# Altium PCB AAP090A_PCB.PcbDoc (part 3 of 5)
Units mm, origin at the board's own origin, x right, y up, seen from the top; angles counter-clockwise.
Board outline 160 x 130 mm, 4 copper layers (Top Layer, Signal Layer 1, Signal Layer 2, Bottom Layer), stack 1.567 mm thick; 507 components, 275 nets, 1462 pads, 1041 vias.
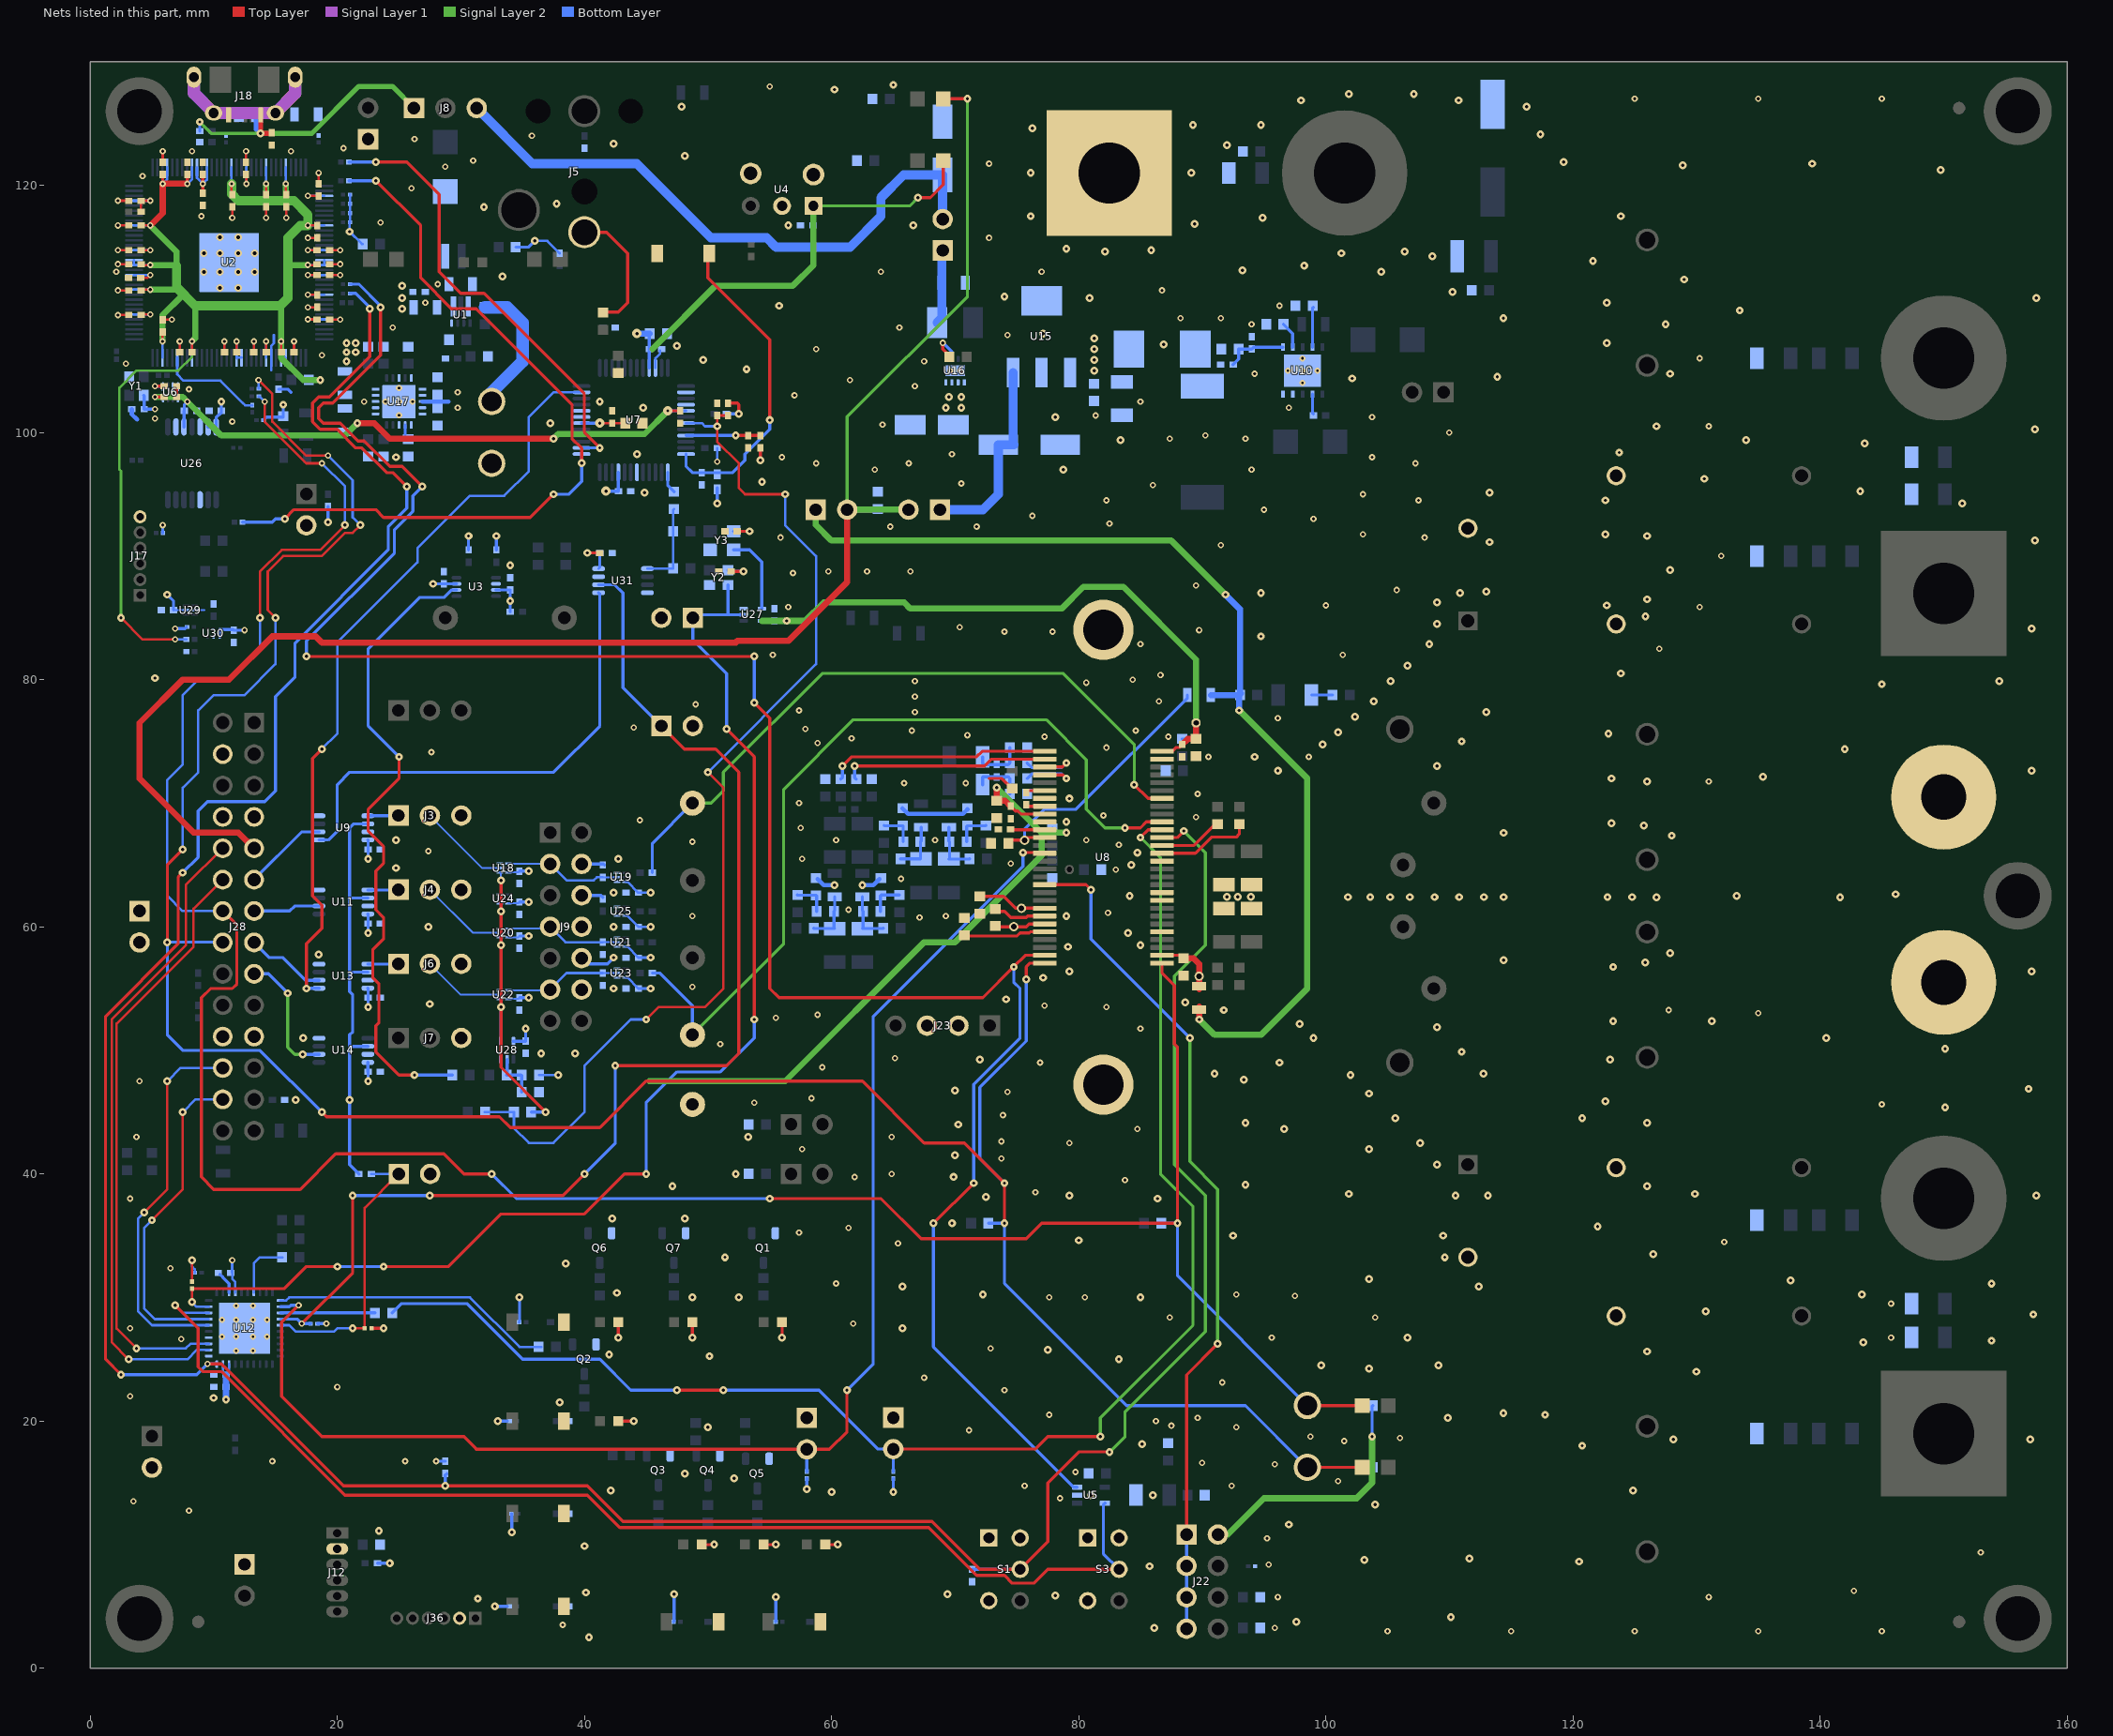
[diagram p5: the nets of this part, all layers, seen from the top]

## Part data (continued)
U27 U28: library part SN74LVC1G14DRLR, "SINGLE SCHMITT-TRIGGER INVERTER, DRL0005A (SOT-5)", Alternate Manufacturer="Texas Instruments"
U29: "DUAL BUFFER/DRIVER WITH OPEN DRAIN OUTPUTS, DSF0006A", Alternate Manufacturer="Texas Instruments"
U30: "Single-Channel, Adjustable Supervisory Circuit in Ultra-Small Package, DRY0006A (USON-6)", Alternate Manufacturer="Texas Instruments", Alternate PartNumber=TPS3897ADRYT
Y1: "OSC, 24 MHz, 2.25 - 3.63 V, SMD", Frequency=24MHz, Frequency Stability=±20ppm, Manufacturer="Abracon Corporation", Supplier Part Number 1=535-13061-1-ND
Y2: "OSC, 24.576 MHz, 2.25 - 3.63 V, SMD", Frequency=24.576MHz, Frequency Stability=±20ppm, Manufacturer="Abracon Corporation", Supplier Part Number 1=535-13231-ND
Y3: "Oscillators, 22.5792MHz, CMOS, 3.3V, SMD", Frequency=22.5792MHz, Frequency Stability=±25ppm, Manufacturer="TXC Corporation", Supplier Part Number 1=887-2303-1-ND
ZZ1 ZZ2 ZZ3: library part AssemblyNote, Alternate Manufacturer=-

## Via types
v1: diameter 0.635, hole 0.254, Top Layer to Bottom Layer, tented both sides, 653 vias
v2: diameter 0.508, hole 0.254, Top Layer to Bottom Layer, tented both sides, 340 vias
v3: diameter 0.5, hole 0.2, Top Layer to Bottom Layer, 24 vias
v4: diameter 0.6, hole 0.3, Top Layer to Bottom Layer, 12 vias
v5: diameter 0.762, hole 0.254, Top Layer to Bottom Layer, tented both sides, 8 vias
v6: diameter 0.457, hole 0.203, Top Layer to Bottom Layer, tented both sides, 4 vias

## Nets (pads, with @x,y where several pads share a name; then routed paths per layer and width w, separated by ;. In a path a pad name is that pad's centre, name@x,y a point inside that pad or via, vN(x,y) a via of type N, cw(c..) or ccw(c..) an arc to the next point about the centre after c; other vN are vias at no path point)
1.0V: C125.1 C126.1 C127.2 C128.2 C129.2 C130.2 C131.2 C132.2 C133.2 C134.2 C135.2 C136.2 C137.2 C138.2 C139.2 C140.2 L1.2 R1.2 R2.2 R140.1 R156.1 U1.4 U2.11 U2.16 U2.17 U2.24 U2.36 U2.41 U2.49 U2.56 U2.60 U2.73 U2.80 U2.81 U2.87 U2.101 U2.102 U2.120 U2.126 | length 126.8
  Top Layer w0.2: v1(2.5,85) 4.25,83.25 v2(6.875,83.25) ; C128.2@4.125,111.5 4.175,111.55 v2(4.875,111.55) ; C129.2@4.125,113.625 4.2,113.55 v2(4.875,113.55) ; C130.2@4.125,116.75 v2(4.875,116.75) ; v2@5.875,107.35 v2(5.85,107.375) 5.85,108.1 C140.2@5.875,108.125 ; v2(5.875,120.125) C135.2@5.875,120.875 ; C139.2@8.25,106.5 v2(8.25,107.375) ; v2(11.45,120.125) 11.45,119.3 C133.2@11.5,119.25 ; C131.2@14.25,119.25 v2(14.25,120.125) ; v2(15.45,107.375) 15.45,106.55 C138.2@15.5,106.5 ; v2(15.85,120.125) 15.85,119.275 C132.2@15.875,119.25 ; v2(17.625,111.15) 18.35,111.15 C137.2@18.375,111.125 ; v2(17.625,113.55) 18.3,113.55 C136.2@18.375,113.625 ; v2(17.625,116.75) C127.2@18.375,116.75
  Top Layer w0.25: v2(7.875,120.125) C134.2@7.875,120.875
  Top Layer w0.5: v2(4.875,116.75) 5.875,117.75 v2(5.875,120.125) v2(7.875,120.125)
  Signal Layer 2 w0.2: v1(2.5,85) 2.5,96.875 2.375,97 2.375,103.625 3.75,105 7.125,105 8.25,106.125 v2(8.25,107.375)
  Signal Layer 2 w0.5: v2(4.875,111.55) 6.8,111.55 7,111.75 ; v2(4.875,113.55) 6.95,113.55 7,113.5 7,114.625 v2(4.875,116.75) ; v2(5.85,107.375) 5.85,109.475 7.5,111.125 ; v2(8.25,107.375) 8.5,107.625 8.5,110.25 ; 14.25,118.75 v2(14.25,120.125) ; 15.375,110.375 15.438,110.312 15.45,110.3 v2(15.45,107.375) 15.45,106.05 17.25,104.25 v1(18.625,104.25) ; v2(15.85,120.125) 15.85,118.9 16,118.75 ; 16,113.5 16.05,113.55 v2(17.625,113.55)
  Signal Layer 2 w0.75: 7,113.5 7,111.75 8.5,110.25 15.375,110.25 15.438,110.312 16,110.875 16,113.5 16,115.75 17,116.75 v2(17.625,116.75) 17.625,117.625 16.5,118.75 16,118.75 14.25,118.75 12,118.75 11.45,119.3 v2(11.45,120.125)
  Bottom Layer w0.2: U2.11@3.55,111.55 v2(4.875,111.55) ; U2.16@3.55,113.55 U2.17@3.55,113.95 ; U2.24@3.55,116.75 v2(4.875,116.75) ; U2.16@3.625,113.55 v2(4.875,113.55) ; U2.126@5.85,106.05 v2(5.85,107.375) ; v2(5.875,120.125) 6.25,120.5 U2.36@6.25,121.45 ; v2(6.875,83.25) R156.1@7.795,83.25 ; v2(7.875,120.125) 8.25,120.5 U2.41@8.25,121.45 ; U2.120@8.25,106.05 v2(8.25,107.375) ; v2(11.45,120.125) U2.49@11.45,121.45 ; v2(14.25,120.125) U2.56@14.25,121.45 ; U2.102@15.45,106.05 15.8,106.05 U2.101@15.85,106 ; U2.102@15.45,106.125 v2(15.45,107.375) ; v2(15.85,120.125) U2.60@15.85,121.45 ; R140.1@17.5,104.05 R140.1@17.7,104.25 v1(18.625,104.25) ; v2(17.625,111.15) U2.87@18.95,111.15 ; v2(17.625,113.55) U2.81@18.95,113.55 U2.80@18.95,113.95 ; v2(17.625,116.75) U2.73@18.95,116.75
  other v1: 25.25,110 25.25,110.875 25.25,111.875
1.8V: C3.1 C89.2 C146.2 C147.2 R8.1 U6.8 U7.17 U17.11 U17.12 U26.3 | length 50.5
  Top Layer w0.25: v2(5.25,102.875) 5.875,102.875 C146.2@6,102.75 ; v5(46.75,101.75) C89.2@47.5,101.75
  Top Layer w0.5: v1(21.625,100.75) 23,100.75 24.25,99.5 v1(37.5,99.5)
  Signal Layer 2 w0.5: v2(5.25,102.875) 7.5,102.875 v2(7.875,102.5) 10.625,99.75 20.625,99.75 v1(21.625,100.75) ; v1(37.5,99.5) 37.875,99.875 44.875,99.875 v5(46.75,101.75)
  Bottom Layer w0.25: v2(5.25,102.875) U6.8@5.875,102.875 ; U26.3@7.6,100.45 7.6,101.75 C147.2@7.625,101.75 7.625,102.25 v2(7.875,102.5) ; v5(46.75,101.75) U7.17@48.225,101.75
3.3V: C17.2 C18.1 C27.2 C37.2 C40.2 C45.2 C54.2 C55.2 C56.2 C58.2 C59.2 C60.1 C61.1 C69.2 C70.2 C71.1 C72.1 C74.2 C80.2 C87.1 C88.2 C90.2 C92.1 C93.1 C94.2 C99.2 C100.2 C101.2 C102.2 C108.2 C109.2 C110.2 C111.2 C112.2 C113.2 C114.2 C115.2 C116.2 C117.2 C118.2 C119.2 C120.2 C121.2 C122.2 C123.2 C143.2 C144.2 C145.2 C148.2 C149.2 C156.2 D4.1 D5.1 D6.1 D7.1 D8.1 D14.1 D15.1 D16.1 J11.1 J16.1 J22.2 J28.7 J28.8 R5.2 R6.1 R11.2 R19.1 R20.1 R22.1 R23.2 R25.1 R38.1 R39.1 R40.1 R41.2 R42.1 R44.1 R45.1 R66.2 R78.2 R79.2 R80.1 R81.2 R82.2 R90.1 R91.1 R92.1 R101.1 R110.1 R114.2 R119.2 R120.2 R124.2 R129.2 R133.2 R136.2 R137.2 R138.2 R139.2 R141.1 R149.1 R150.1 R155.1 R165.2 R167.1 TP12.1 U2.6 U2.14 U2.19 U2.29 U2.42 U2.44 U2.52 U2.67 U2.78 U2.83 U2.92 U2.105 U2.110 U2.111 U3.3 U3.7 U4.1 U6.1 U7.9 U7.33 U7.42 U8.9 U8.56 U9.8 U11.8 U12.14 U12.38 U12.39 U13.8 U14.8 U17.14 U17.15 U18.6 U19.6 U20.6 U21.6 U22.6 U23.6 U24.6 U25.6 U26.6 U26.7 U27.5 U28.5 U29.5 U30.1 U30.6 U31.8 Y1.4 Y2.4 Y3.4 | length 309.9
  Top Layer w0.2: C100.2@4.1,112.5 4.625,112.5 v2(4.875,112.75) ; C80.2@4.125,109.5 4.175,109.55 v2(4.875,109.55) ; C99.2@4.125,114.75 v2(4.875,114.75) ; R110.1@4.125,117.875 C102.2@4.125,118.75 v2(4.875,118.75) ; 8.25,31.5 v1(8.25,33) ; v2(11.85,107.375) 11.85,106.525 C54.2@11.875,106.5 ; C27.2@12.625,120.875 12.65,120.85 v2(12.65,120.125) ; C74.2@14.25,106.5 v2(14.25,107.375) ; v2(17.625,109.15) 18.35,109.15 C58.2@18.375,109.125 ; v2(17.625,112.75) C101.2@18.375,112.75 ; v2(17.625,114.75) C40.2@18.375,114.75 ; v2(17.625,119.15) 18.475,119.15 C45.2@18.5,119.125 ; v1(40.25,90.25) R82.2@41.25,90.25 ; v5(41.25,100.75) C88.2@42.25,100.75 C87.1@43.3,100.75
  Top Layer w0.25: v2(5.25,103.75) C144.2@5.875,103.75 ; C17.2@9.125,119.375 v2(9.125,120.125) C37.2@9.125,120.875 ; R5.2@22.78,27.5 v1(23.75,27.5) ; D4.1@42.75,20 v1(44,20) ; v1(42.75,26.75) D8.1@42.75,28 ; v1(48.75,26.75) D15.1@48.75,28 ; D5.1@49.5,10 v1(50.5,10) ; R120.2@51.625,102.375 52.375,102.375 52.5,102.25 v1(52.5,101.5) ; C118.2@51.875,88.75 v1(52.875,88.75) ; C119.2@52.375,92 v1(53.375,92) ; v1(54.25,97.75) R119.2@54.25,98.75 ; D6.1@54.5,10 v1(55.5,10) ; v1(56,26.75) D16.1@56,28 ; D7.1@59.5,10 v1(60.5,10) ; v1(67,119) 68,119 69.05,120.05 D14.1@69.05,122 ; C72.1@74.5,69.75 74.875,69.375 75.075,69.375 75.333,69.117 U8.9@77.25,69.117 ; U8.56@86.75,74.197 87.572,74.197 87.875,74.5 88.125,74.5 C61.1@88.375,74.75
  Top Layer w0.5: C71.1@73.325,70.25 C71.1@73.375,70.2 74.05,70.2 C72.1@74.5,69.75 ; C71.1@73.375,70.25 v1(73.375,71.25) ; C61.1@88.375,74.75 88.825,75.2 C60.1@89.5,75.2 TP12.1@89.5,76.5
  Signal Layer 2 w0.25: U4.1@58.54,118.33 66.33,118.33 v1(67,119)
  Signal Layer 2 w0.5: 45.25,47.5 56.25,47.5 67.5,58.75 70,58.75 77,65.75 77,67.625 ; 45.5,106.75 50.625,111.875 56.875,111.875 58.54,113.54 U4.1@58.54,118.33 ; 54.375,84.75 v1(56.375,84.75) 57.875,84.75 59.375,86.25 65.875,86.25 66.375,85.75 78.625,85.75 80.375,87.5 83.625,87.5 89.5,81.625 TP12.1@89.5,76.5 ; v1(73.375,71.25) 77,67.625 ; v1(79,67.625) 77,67.625 ; J22.2@91.27,10.81 92.06,10.81 95,13.75 102.5,13.75 103.75,15 v1(103.75,18.75)
  Bottom Layer w0.15: C149.2@6.75,85.625 U29.5@7.785,85.625 ; U22.6@33.84,54.15 34.65,54.15 C110.2@34.75,54.25 ; U20.6@33.84,59.15 34.65,59.15 C111.2@34.75,59.25 ; U24.6@33.84,61.9 34.65,61.9 C112.2@34.75,62 ; U18.6@33.84,64.4 34.65,64.4 C113.2@34.75,64.5
  Bottom Layer w0.2: U2.6@3.55,109.55 v2(4.875,109.55) ; U2.14@3.55,112.75 v2(4.875,112.75) ; U2.19@3.55,114.75 v2(4.875,114.75) ; U2.29@3.55,118.75 v2(4.875,118.75) ; v1(8.25,33) 8.25,32.5 8.47,32.28 R114.2@8.47,32 ; U2.42@8.65,121.45 8.65,120.6 v2(9.125,120.125) 9.45,120.45 U2.44@9.45,121.45 ; U12.39@10.75,24.6 10.75,24 C56.2@11,23.75 11.25,24 U12.38@11.25,24.6 ; C120.2@11.5,32 11.5,31.5 11.75,31.25 U12.14@11.75,30.4 ; U2.111@11.85,106.05 v2(11.85,107.375) ; U2.111@11.875,106 11.925,106.05 U2.110@12.25,106.05 ; v2(12.65,120.125) U2.52@12.65,121.45 ; U2.105@14.25,106.05 v2(14.25,107.375) ; v2(17.625,109.15) U2.92@18.95,109.15 ; v2(17.625,112.75) U2.83@18.95,112.75 ; v2(17.625,114.75) U2.78@18.95,114.75 ; v2(17.625,119.15) U2.67@18.95,119.15 ; R139.2@21,117 21.03,117.03 R138.2@21.03,117.75 ; R138.2@21,117.75 21.03,117.78 R137.2@21.03,118.5 ; R137.2@21,118.5 21.03,118.53 R136.2@21.03,119.25 ; R139.2@21.03,117 21,116.97 v1(21,116.25) 22,115.25 R141.1@22.05,115.25 ; v1(36,115.5) 37,115.5 R23.2@38,114.5 ; R11.2@36.325,48 v1(37.875,48) ; v1(40.25,90.25) C156.2@41.25,90.25 41.25,89.075 U31.8@41.15,88.975 ; U23.6@43.34,55.9 43.475,55.9 C117.2@44.375,55 v1(45.375,55) ; U21.6@43.34,58.4 43.475,58.4 C116.2@44.375,57.5 v1(45.375,57.5) ; U25.6@43.34,60.9 43.475,60.9 C114.2@44.375,60 v1(45.375,60) ; U19.6@43.34,63.65 43.475,63.65 C115.2@44.375,62.75 v1(45.375,62.75) ; v2(50.75,97.625) R22.1@50.75,98.75 ; C18.1@58.5,116.75 58.5,118.25 U4.1@58.625,118.375 ; R165.2@88.375,75.2 89.2,75.2 89.5,75.5 TP12.1@89.5,76.5
  Bottom Layer w0.25: Y1.4@4.35,103 4.375,102.975 C143.2@4.375,101.875 v2(5.25,101.875) ; v2(5.25,103.75) U6.1@5.875,103.75 ; R149.1@5.875,91.875 v2(5.875,92.5) ; v1(6.25,86.875) 6.75,86.375 C149.2@6.75,85.625 ; v2(6.875,84.125) 7.67,84.125 R155.1@7.795,84.25 ; U26.6@9.55,100.45 U26.7@10.2,100.45 10.2,101.2 10.625,101.625 C145.2@10.625,101.75 v1(10.625,102.5) ; U30.1@10.5,83.475 U30.6@10.5,84.05 11.575,84.05 C148.2@11.625,84 v2(12.5,84) ; C120.2@11.5,32 v2(11.5,33) ; R150.1@14.03,101 14.28,101.25 R167.1@15.625,101.25 ; R167.1@15.625,101.325 v1(15.625,102.25) ; R66.2@18.405,27.875 v2(19.125,27.875) ; v1(19.25,92.75) R80.1@19.25,94 ; U14.8@22.475,49.025 22.475,48.275 C108.2@22.5,48.25 v1(22.5,47.5) ; U13.8@22.475,55.025 22.5,55 C70.2@22.5,54.25 v1(22.5,53.5) ; U11.8@22.475,61.025 22.5,61 C69.2@22.5,60.25 v1(22.5,59.5) ; U9.8@22.475,67.025 22.5,67 C59.2@22.5,66.25 v1(22.5,65.5) ; R41.2@23.25,8.5 v1(24.25,8.5) ; v1(27.75,87.75) C121.2@28.625,87.75 U3.7@29.65,87.75 ; v2(28,16.75) R92.1@28.75,16.75 ; R124.2@30.625,90.5 v1(30.625,91.625) ; v1(32.75,5) 33.75,5 ; U3.3@32.85,87.25 C123.2@34,87.25 v1(34,86.375) R81.2@34,85.5 ; R133.2@32.875,90.5 v1(32.875,91.625) ; v1(33,20) 33.75,20 ; R40.1@34.095,12.5 34.125,12.47 v1(34.125,11) ; U28.5@34.25,50.74 35.24,50.74 C109.2@35.25,50.75 v1(35.25,51.75) ; R19.1@34.45,115 35.5,115 v1(36,115.5) ; R38.1@34.72,28 34.75,28.03 v1(34.75,30) ; C110.2@34.75,54.25 v1(35.5,54.25) ; C111.2@34.75,59.25 v1(35.5,59.25) ; C112.2@34.75,62 v1(35.5,62) ; C113.2@34.75,64.5 v1(35.5,64.5) ; U7.42@39.775,100.75 v5(41.25,100.75) ; v5(41.75,95.25) C90.2@42.75,95.25 U7.33@42.75,96.775 ; U7.9@45.25,105.225 45.25,107.95 C93.1@45.3,108 ; R45.1@47.22,3.75 47.25,3.78 v1(47.25,6) ; v1(50.75,94.25) R25.1@50.75,95.5 ; R20.1@51.5,101.5 v1(52.5,101.5) ; Y2.4@51.625,88.85 51.725,88.75 v1(52.875,88.75) ; Y3.4@52.075,92 v1(53.375,92) ; U27.5@54.365,84.75 C122.2@55.375,84.75 v1(56.375,84.75) ; R44.1@55.47,3.75 55.5,3.78 v1(55.5,5.75) ; v1(58,14.5) R90.1@58,15.345 R90.1@58,15.375 ; v1@65,14.5 R91.1@65,15.345 R91.1@65,15.375 ; R101.1@77.875,67.95 78.2,67.625 v1(79,67.625) ; R79.2@103.8,16.25 103.75,16.3 v1(103.75,18.75) 103.75,21.2 R78.2@103.8,21.25
  Bottom Layer w0.5: v1(11,21.75) C55.2@11,22.75 C56.2@11,23.75 ; v5(44.25,108) C93.1@45.3,108
  other v1: 65,14.25 20.75,105.75 20.75,106.5 21.5,106.5 20.75,107.25 21.5,107.25
5V: C2.1 C91.1 C124.1 D17.1 R63.1 TP5.1 U1.7 U17.1 U17.2 U17.4 U17.5 U17.6 U17.20 | length 11
  Bottom Layer w1: R63.1@31.95,110.15 31.975,110.125 33.75,110.125 35,108.875 35,105.75 32.5,103.25 TP5.1@32.5,102.5
5V-USB: C142.2 J8.1 J18.1 R145.2 R157.2 | length 24.7
  Top Layer w0.4: J18.1@13.8,125.7 v1(13.8,124.2) R157.2@14.7,124.2
  Signal Layer 2 w0.25: v1(8.875,125.125) 9.375,124.625 9.8,124.2 v1(13.8,124.2)
  Signal Layer 2 w0.4: v1(13.8,124.2) 17.95,124.2 21.75,128 24.46,128 J8.1@26.21,126.25
  Bottom Layer w0.25: R145.2@8.875,124.375 v1(8.875,125.125)
  Bottom Layer w0.4: C142.2@13.45,125.55 13.45,124.55 v1(13.8,124.2)
5V-VR: C86.1 J8.3 J29.2 | length 49.3
  Bottom Layer w0.75: J8.3@31.29,126.25 35.79,121.75 44.25,121.75 50.25,115.75 54.75,115.75 55.5,115 61.5,115 64,117.5 64,119 65.85,120.85 C86.1@69,120.85 J29.2@69,117.27
12V: C84.2 D13.1 J20.2 J27.2 J28.9 | length 130.8
  Top Layer w0.25: D13.1@69.05,127 v1(71,127)
  Top Layer w0.5: J28.9@13.27,66.35 11.995,67.625 8.375,67.625 4,72 4,76.5 7.5,80 11.25,80 14.75,83.5 18.25,83.5 18.75,83 52.25,83 52.375,83.125 56.5,83.125 61.25,87.875 J20.2@61.25,93.5
  Signal Layer 2 w0.25: J20.2@61.27,93.75 61.27,101.27 71,111 v1(71,127)
  Signal Layer 2 w0.5: J20.2@61.27,93.75 J27.2@66.23,93.75
  Bottom Layer w0.5: J20.2@61.27,93.75 C84.2@63.75,93.75
15V: C38.1 C83.1 C85.1 J25.2 U15.1 U16.2 U16.3
  other v1: 69.25,102 70.5,102 69.5,102.875 70.5,102.875 81.25,105 81.25,105.875 81.25,106.75 81.25,107.625
15V-VR: C34.1 J25.1 L9.2 R58.2
\CLIP_OTW: D9.2 J28.14 R104.2 R163.1 TP15.1 U8.29 | length 212.9
  Top Layer w0.2: v1(13.75,85) 13.75,88.75 15.5,90.5 18.625,90.5 v1(20.625,92.5) ; v2(14.125,102.5) 14.125,100.875 17.5,97.5 v2(18.75,97.5)
  Top Layer w0.25: J28.14@10.73,61.27 11.875,60.125 11.875,55.375 11.5,55 9.75,55 9,54.25 9,39.75 10,38.75 17,38.75 19.875,41.625 28.625,41.625 30.25,40 v1(32.5,40) ; v1(55,38) 64,38 67.25,34.75 75.75,34.75 77,36 v1(88,36) 88,50.25 87.75,50.5 87.75,55.25 86.75,56.25 U8.29@86.75,57.052 ; TP15.1@98.5,21.25 D9.2@102.95,21.25
  Bottom Layer w0.2: J28.14@10.73,61.27 7.48,61.27 6.25,62.5 6.25,71.875 7.5,73.125 7.5,78.75 8.75,80 11.25,80 11.375,80.125 13.75,82.5 v1(13.75,85) ; R163.1@13.655,102.92 13.705,102.92 v2(14.125,102.5) ; v2(18.75,97.5) 20.625,95.625 v1(20.625,92.5)
  Bottom Layer w0.25: v1(32.5,40) 34.5,38 v1(55,38) ; R104.2@86.7,36 v1(88,36) 88,31.75 TP15.1@98.5,21.25
\DAC_MUTE: C151.2 R92.2 R161.1 S1.5 U8.45 U12.40 | length 266.7
  Top Layer w0.25: v1(2.5,23.75) 1.25,25 1.25,52.75 7.125,58.625 7.125,64 v1(7.5,64.375) ; v2(9.5,24.625) 10.625,24.625 10.8,24.45 10.811,24.45 20.511,14.75 v1(28.75,14.75) 40.25,14.75 43.125,11.875 68.125,11.875 72,8 S1.5@75.27,8 77.5,10.23 77.5,15 80,17.5 v1(82.5,17.5) ; v1(22.625,110) 22.625,106.125 19.375,102.875 18.5,102.875 18,102.375 18,100.875 18.625,100.25 20,100.25 21.5,98.75 22,98.75 24,96.75 24.5,96.75 v1(25.625,95.625) ; U8.45@86.75,67.212 87.963,67.212 v1(88.5,67.75)
  Signal Layer 2 w0.25: v1(82.5,17.5) 83.75,18.75 83.75,20.75 90.25,27.25 90.25,38.25 87.75,40.75 87.75,56 90.25,58.5 90.25,66 v1(88.5,67.75)
  Bottom Layer w0.25: v1(2.5,23.75) 8.625,23.75 v2(9.5,24.625) 10.225,24.625 U12.40@10.25,24.6 ; v1(7.5,64.375) 8.75,65.625 8.75,69.375 9.5,70.125 14.125,70.125 15,71 15,78.625 16.581,80.206 16.581,82.956 24.125,90.5 24.125,92.375 25.625,93.875 v1(25.625,95.625) ; R161.1@21.03,111.25 21.5,111.25 22.625,110.125 v1(22.625,110) ; v1(28.75,14.75) 28.75,15.625 R92.2@28.875,15.75 ; C151.2@71.375,8 S1.5@75.27,8
\FAULT: D10.2 J28.16 R103.2 R162.1 TP16.1 U8.28 | length 215.1
  Top Layer w0.2: v2(13.625,104.25) 14.75,103.125 14.75,100.875 17.499,98.126 v2(19.25,98.126) ; v1(15,85) 14.375,85.625 14.375,88.75 15.625,90 18.75,90 20.625,91.875 21.25,91.875 v1(21.875,92.5)
  Top Layer w0.25: v1(6.25,58.75) 6.25,65 v1(7.5,66.25) ; v1(18.75,45) 19.125,44.625 33.125,44.625 34,43.75 41.25,43.75 45,47.5 62.5,47.5 67.5,42.5 70.75,42.5 v1(74,39.25) v1(74,36) ; v1(75.75,55.75) 75.75,56.75 76.052,57.052 U8.28@77.25,57.052 ; TP16.1@98.5,16.25 D10.2@102.95,16.25
  Bottom Layer w0.2: v1@7.5,66.375 7.5,71.25 8.75,72.5 8.75,77.5 10,78.75 12.5,78.75 15,81.25 v1(15,85) ; v2(13.625,104.25) 13.625,103.575 R162.1@13.655,103.545 ; v2(19.25,98.126) v2@19.374,98.126 ; v2@19.375,98.125 19.375,98 21.25,96.125 21.25,93.125 v1(21.875,92.5)
  Bottom Layer w0.25: J28.16@10.73,58.73 10.71,58.75 v1(6.25,58.75) 6.25,51.25 7.515,49.985 13.765,49.985 v1(18.75,45) ; R103.2@72.7,36 v1(74,36) 74,31.125 83.875,21.25 93.5,21.25 TP16.1@98.5,16.25 ; v1(74,39.25) 72,41.25 72,47 75.75,50.75 v1(75.75,55.75)
\FREQ-SEL: U27.4 Y3.1 | length 6.5
  Bottom Layer w0.25: Y3.1@52.075,90.5 53.375,90.5 54.365,89.51 U27.4@54.365,85.75
\I2S-BUF-EN: R168.2 U18.1 U20.1 U22.1 U24.1 U28.4 | length 26.9
  Top Layer w0.25: v1(33.25,63.75) v1(33.25,61.25) v1(33.25,58.5) v1(33.25,53.5) 33.25,48.625 v1(36.875,45)
  Bottom Layer w0.15: U22.1@33.16,54.15 33.25,54.06 v1(33.25,53.5) ; U20.1@33.16,59.15 33.25,59.06 v1(33.25,58.5) ; U24.1@33.16,61.9 33.25,61.81 v1(33.25,61.25) ; U18.1@33.16,64.4 33.25,64.31 v1(33.25,63.75)
  Bottom Layer w0.25: U28.4@33.25,50.74 v1(33.25,53.5) ; R168.2@35.7,45 v1(36.875,45)
\MUTE-AIB: J28.12 U12.3 | length 48.2
  Top Layer w0.2: v1(3.75,25.875) 2.15,27.475 2.15,52.15 8.375,58.375 8.375,61.455 J28.12@10.73,63.81
  Bottom Layer w0.2: v1(3.75,25.875) 7.75,25.875 8.125,26.25 U12.3@9.6,26.25
\RESET-AMP: R160.1 U5.3 U8.27 | length 180.9
  Top Layer w0.25: v1(17.5,81.875) v1(53.75,81.875) ; v1(23.5,110.125) 23.5,106.25 19.625,102.375 18.875,102.375 18.5,102 18.5,101.125 18.875,100.75 20.25,100.75 21.688,99.312 22.188,99.312 24.25,97.25 25.25,97.25 v1(26.875,95.625) ; v1(53.75,78.125) 55,76.875 55,55 55.75,54.25 72.25,54.25 v1(74.75,56.75) 75.687,57.687 U8.27@77.25,57.687 ; v1(68.25,36) v1(71.5,39.25)
  Bottom Layer w0.25: v1(17.5,81.875) 17.5,83.125 24.625,90.25 24.625,92.125 26.125,93.625 26.125,94.875 v1(26.875,95.625) ; R160.1@21.03,112 21.75,112 23.5,110.25 v1(23.5,110.125) ; v1(53.75,78.125) v1(53.75,81.875) ; v1(68.25,36) 68.25,26 79.6,14.65 U5.3@79.875,14.65 ; v1(71.5,39.25) 71.5,47.25 75.25,51 75.25,55 74.75,55.5 v1(74.75,56.75)
\RST-AIB: J28.10 U12.2 | length 52.4
  Top Layer w0.2: v1(3.125,25) 1.75,26.375 1.75,52.5 7.75,58.5 7.75,63.37 J28.10@10.73,66.35
  Bottom Layer w0.2: v1(3.125,25) 7.875,25 8.625,25.75 U12.2@9.6,25.75
\RST-AMP: S3.5 U5.5 U12.8 | length 96.9
  Top Layer w0.25: v1(6.875,29.375) 8.75,27.5 8.75,24.375 9.125,24 10.625,24 20.625,14 40.25,14 42.875,11.375 67.875,11.375 71.75,7.5 74,7.5 74.625,6.875 76.375,6.875 77.5,8 S3.5@83.27,8
  Bottom Layer w0.2: v1(6.875,29.375) 7.5,28.75 U12.8@9.6,28.75
  Bottom Layer w0.25: U5.5@82.125,13.35 82,13.225 82,9.27 S3.5@83.27,8
\SPDIF-RESET: C24.2 R25.2 S2.2 U7.24 | length 26.1
  Top Layer w0.25: S2.2@50.1,114.5 50,114.4 50,112.5 55,107.5 v1(55,101)
  Bottom Layer w0.25: U7.24@48.225,98.25 48.225,97.275 48.75,96.75 C24.2@49.5,96.75 52,96.75 53,97.75 53,98.25 55,100.25 v1(55,101)
\TRST: R147.1 U2.123 | length 8.5
  Bottom Layer w0.2: U2.123@7.05,106.05 7.05,104.7 7.55,104.2 10.55,104.2 12.375,102.375 12.55,102.2 R147.1@13.125,102.2
A0-SRC: R10.1 R120.1 R122.1 R168.1 U7.19 | length 87.7
  Top Layer w0.2: v1(45,52.5) 46,53.5 49.75,53.5 51.25,55 51.25,71.25 v1(50,72.5) ; R120.1@51.625,101.375 R122.1@50.75,101.375 v1(50.75,100.5) 50.75,99.25 52.5,97.5 52.5,95.5 53,95 v1(56.25,95)
  Bottom Layer w0.2: R10.1@31.95,45 R168.1@34.3,45 34.3,43.7 35.5,42.5 37.5,42.5 40,45 40,48.75 43.75,52.5 v1(45,52.5) ; U7.19@48.225,100.75 49.5,100.75 49.75,100.5 v1(50.75,100.5) ; v1(50,72.5) 58.75,81.25 58.75,90 56.25,92.5 v1(56.25,95)
A1-SRC: R119.1 R121.1 U7.21 | length 6
  Top Layer w0.25: v1(52.25,99.75) R121.1@53.25,99.75 R119.1@54.25,99.75
  Bottom Layer w0.25: U7.21@48.225,99.75 v1(52.25,99.75)
ADR: J19.2 R62.1 R91.2 U8.46 | length 120.1
  Top Layer w0.25: v1(47.5,22.5) v1(51.25,22.5) ; J19.2@65,17.73 76.48,17.73 77.5,18.75 v1(81.75,18.75) ; v1(85,67.222) 85.625,67.847 U8.46@86.75,67.847
  Signal Layer 2 w0.25: v1(81.75,18.75) 81.75,20.25 89.25,27.75 89.25,37.375 86.625,40 86.625,65.597 v1(85,67.222)
  Bottom Layer w0.25: R62.1@24.45,28.75 25.2,29.5 30.5,29.5 35,25 41.25,25 43.75,22.5 v1(47.5,22.5) ; v1(51.25,22.5) 59,22.5 63.77,17.73 J19.2@65,17.73 R91.2@65,15.905
ADR-MCU: R62.2 U12.23 | length 7.7
  Bottom Layer w0.25: U12.23@15.4,28.75 R62.2@23.05,28.75
AVDD: C63.2 TP11.1 U8.23 | length 4.1
  Top Layer w0.25: C63.2@73.25,60.05 73.3,60 TP11.1@74.75,60 75.75,60 75.978,60.227 U8.23@77.25,60.227
BCLK-EXT: J28.13 U11.2 | length 5.4
  Bottom Layer w0.25: J28.13@13.27,61.27 16.145,61.27 16.55,61.675 U11.2@18.525,61.675
BCLK-IBC: J9.7 R116.2 U20.4 U21.2 | length 9.4
  Bottom Layer w0.15: U20.4@33.84,59.85 37.08,59.85 J9.7@37.23,60 ; R116.2@41.5,58.75 U21.2@42.66,58.75
  Bottom Layer w0.2: J9.7@37.23,60 38.48,58.75 R116.2@41.5,58.75
BCLK-MUX: J4.1 U11.5 | length 2.5
  Bottom Layer w0.25: U11.5@22.475,62.975 24.935,62.975 J4.1@24.96,63
BCLK-PSIA: J4.2 U20.2 | length 7.1
  Bottom Layer w0.15: J4.2@27.5,63 31,59.5 U20.2@33.16,59.5
BCLK-USB: R143.1 R151.1 U7.37 | length 64.6
  Top Layer w0.25: v1(15.75,93) 16.5,93.75 23.125,93.75 23.75,93.125 35.625,93.125 v1(37.5,95) ; v1(23.125,120.375) 26.75,116.75 26.75,112.5 29.25,110 31.25,110 39,102.25 39,99.5 39.775,98.725 v1(39.775,97.525)
  Bottom Layer w0.25: R151.1@12.33,92.75 14.75,92.75 15,93 v1(15.75,93) ; R143.1@20.955,120.375 v1(23.125,120.375) ; v1(37.5,95) 38.75,95 39.775,96.025 v1(39.775,97.525) U7.37@39.775,98.25
C_START: C78.1 U8.24 | length 6.7
  Top Layer w0.25: C78.1@70.75,59.3 70.8,59.25 75,59.25 75.25,59.5 76,59.5 76.092,59.592 U8.24@77.25,59.592 U8.24@77.282,59.625
COAX-LED: R109.2 U12.17 | length 4.9
  Bottom Layer w0.2: U12.17@13.25,30.4 13.25,32.75 13.75,33.25 R109.2@15.55,33.25
DAC_OUTA+: R95.1 U8.3 | length 5.4
  Top Layer w0.25: U8.3@77.25,72.927 78.677,72.927 v1(79,73.25)
  Bottom Layer w0.25: R95.1@75.825,73.25 76.2,72.875 78.625,72.875 v1(79,73.25)
DAC_OUTA-: R98.1 U8.4 | length 5.4
  Top Layer w0.25: U8.4@77.25,72.292 78.708,72.292 v1(79,72)
  Bottom Layer w0.25: R98.1@75.825,72 76.2,72.375 78.625,72.375 v1(79,72)
DAC_OUTB+: R69.1 U8.1 | length 18
  Top Layer w0.25: v1(60.875,73) 61.625,73.75 71.75,73.75 72.197,74.197 U8.1@77.25,74.197
  Bottom Layer w0.25: R69.1@60.75,71.95 60.875,72.075 v1(60.875,73)
DAC_OUTB-: R67.1 U8.2 | length 16.7
  Top Layer w0.25: v1(61.875,73) 72.375,73 72.937,73.562 U8.2@77.25,73.562
  Bottom Layer w0.25: v1(61.875,73) 61.875,72.075 R67.1@62,71.95
DIN-EXT: J28.17 U14.2 | length 10.5
  Signal Layer 2 w0.25: v1(16,54.625) 16,50.25 16.575,49.675 v1(17.2,49.675)
  Bottom Layer w0.25: J28.17@13.27,56.19 14.435,56.19 v1(16,54.625) ; v1(17.2,49.675) U14.2@18.525,49.675
DVDD: C65.2 TP13.1 U8.21 | length 5.8
  Top Layer w0.25: C65.2@72,62.45 73.925,62.45 74.875,61.5 TP13.1@75.375,61.5 75.377,61.497 U8.21@77.25,61.497 ; U8.21@77.25,61.5 U8.21@77.375,61.5
FREQ-SEL: J2.1 R129.1 U12.9 U27.2 Y2.1 | length 102.3
  Top Layer w0.2: v1(8.25,29.625) 8.25,30.5
  Top Layer w0.25: R129.1@8.25,30.72 15.72,30.72 17.5,32.5 v1(20,32.5) ; v1(23.75,32.5) 29,32.5 33.25,36.75 40,36.75 43.25,40 v1(45,40) ; v1(51.5,76) 53.75,73.75 v1(53.75,52.5)
  Bottom Layer w0.2: v1(8.25,29.625) 8.625,29.25 U12.9@9.6,29.25
  Bottom Layer w0.25: v1(20,32.5) v1(23.75,32.5) ; v1(45,40) 45,45.75 47.5,48.25 51,48.25 53.75,51 v1(53.75,52.5) ; v1(51.5,76) 51.5,80.5 48.77,83.23 J2.1@48.77,85 49.02,85.25 51.625,85.25 ; Y2.1@51.625,87.65 51.625,85.25 ; U27.2@52.885,85.25 51.625,85.25
FREQ_ADJ: J22.1 J22.3 J22.5 J22.7 U8.18 | length 69
  Top Layer w0.25: U8.18@77.25,63.402 80.598,63.402 v1(81,63) ; J22.1@88.73,10.81 88.73,23.73 v1(91.25,26.25)
  Signal Layer 2 w0.25: v1(89,51) 89,41 91.25,38.75 v1(91.25,26.25)
  Bottom Layer w0.25: v1(81,63) 81,59 v1(89,51) ; J22.7@88.73,3.19 J22.5@88.73,5.73 J22.3@88.73,8.27 J22.1@88.73,10.81
GND: C1.2 C2.2 C3.2 C4.1 C17.1 C18.2 C19.1 C21.2 C22.2 C23.2 C24.1 C25.2 C27.1 C28.1 C29.1 C30.2 C31.2 C32.1 C33.2 C35.2 C36.2 C37.1 C38.2 C39.2 C40.1 C41.1 C42.1 C43.2 C44.2 C45.1 C47.2 C48.2 C49.2 C50.2 C51.2 C52.1 C53.2 C54.1 C55.1 C56.1 C57.2 C58.1 C59.1 C60.2 C61.2 C63.1 C64.2 C65.1 C67.2 C69.1 C70.1 C71.2 C72.2 C73.2 C74.1 C78.2 C79.2 C80.1 C81.2 C82.2 C83.2 C84.1 C85.2 C86.2 C87.2 C88.1 C89.1 C90.1 C91.2 C92.2 C93.2 C94.1 C95.1 C96.2 C97.1 C99.1 C100.1 C101.1 C102.1 C107.1 C108.1 C109.1 C110.1 C111.1 C112.1 C113.1 C114.1 C115.1 C116.1 C117.1 C118.1 C119.1 C120.1 C121.1 C122.1 C123.1 C124.2 C125.2 C126.2 C127.1 C128.1 C129.1 C130.1 C131.1 C132.1 C133.1 C134.1 C135.1 C136.1 C137.1 C138.1 C139.1 C140.1 C141.2 C142.1 C143.1 C144.1 C145.1 C146.1 C147.1 C148.1 C149.1 C150.1 C151.1 C152.1 C153.1 C154.1 C155.1 C156.1 H1.1 H1.2 J1.2 J2.2 J3.3 J4.3 J6.3 J7.3 J9.4 J9.6 J9.8 J9.10 J9.12 J12.2 J13.1 J14.1 J17.6 J19.1 J21.1 J23.2 J23.3 J24.1 J28.4 J28.21 J28.22 J33.2 J34.1 J34.2 J35.2 J36.2 J37.2 L2.2 L4.2 Q1.2 Q2.2 Q3.2 Q4.2 Q5.2 Q6.2 Q7.2 R3.1 R7.1 R9.1 R12.1 R29.1 R37.1 R59.1 R60.1 R64.1 R65.1 R71.1 R74.1 R75.1 R76.1 R77.1 R84.1 R85.2 R86.2 R87.1 R88.1 R89.1 R93.1 R94.1 R97.1 R99.1 R100.1 R102.1 R115.1 R116.1 R117.1 R118.1 R121.2 R122.2 R123.2 R144.1 R148.1 R157.1 R158.2 R166.1 S1.1 S1.3 S1.4 S2.1 S3.1 S3.3 S3.4 S4.1 S5.1 S6.1 S7.1 S8.1 S9.1 TP6.1 TP23.1 U1.5 U2.104 U2.129 U3.2 U4.2 U4.4 U4.5 U5.2 U6.3 U6.4 U6.5 U7.10 U7.14 U7.16 U7.30 U7.43 U7.44 U8.7 U8.10 U8.22 U8.33 U8.37 U8.38 U8.42 U8.55 U9.4 U9.7 U10.4 U10.5 U10.11 U11.4 U11.7 U12.1 U12.4 U12.13 U12.41@12.5,27.5 U13.4 U13.7 U14.4 U14.7 U15.2 U15.4 U16.1 U16.4 U16.5 U16.9 U17.3 U17.8 U17.13 U17.18 U17.21@25,102.5 U18.3 U19.1 U19.3 U20.3 U21.1 U21.3 U22.3 U23.1 U23.3 U24.3 U25.1 U25.3 U26.2 U26.5 U26.10 U27.3 U28.3 U29.2 U30.2 U31.4 U31.7 Y1.2 Y2.2 Y3.2 | length 54.1
  Top Layer w0.2: v2(2.25,109.5) C80.1@3.125,109.5 ; v2(2.25,111.5) C128.1@3.125,111.5 ; v2(2.25,113.625) C129.1@3.125,113.625 ; v2(2.25,114.75) C99.1@3.125,114.75 ; v2(2.25,116.75) C130.1@3.125,116.75 ; v2(2.25,118.75) C102.1@3.125,118.75 ; C140.1@5.875,109.125 v2(6.625,109.125) ; C135.1@5.875,121.875 v2(5.875,122.75) ; C139.1@7.25,106.5 v2(7.25,107.375) ; C54.1@10.875,106.5 v2(10.875,107.375) ; v2(11.5,117.375) C133.1@11.5,118.25 ; C27.1@12.625,121.875 v2(12.625,122.75) ; C74.1@13.25,106.5 v2(13.25,107.375) ; v2(14.25,117.375) C131.1@14.25,118.25 ; v2(15.875,117.375) C132.1@15.875,118.25 ; C138.1@16.5,106.5 v2(16.5,107.375) ; v2(17.625,110.125) C137.1@18.5,110.125 ; v2(17.625,115.75) C127.1@18.5,115.75 ; C45.1@18.5,120.125 v2(18.5,121) ; C58.1@19.375,109.125 v2(20.25,109.125) ; C101.1@19.375,112.75 v2(20.25,112.75) ; C136.1@19.375,113.625 v2(20.25,113.625) ; C40.1@19.375,114.75 v2(20.25,114.75)
  Top Layer w0.25: C146.1@7,102.875 C144.1@7,103.75 ; 72.75,72 73.8,72 C107.1@74.625,71.175 ; C63.1@73.25,61.45 73.45,61.25 74,61.25 74.5,60.75 75.75,60.75 75.863,60.862 U8.22@77.25,60.862
  Bottom Layer w0.15: U29.2@8.465,85.625 9.25,85.625
  Bottom Layer w0.2: 14.65,105.025 U2.104@14.65,106.05 14.65,106.992 14.875,107.217 14.875,107.875 ; U7.10@45.75,105.225 45.75,106 46.125,106.375 C94.1@46.125,106.625
  Bottom Layer w0.25: C120.1@10.5,31.875 10.75,31.625 10.75,31.615 11.25,31.115 U12.13@11.25,30.4 ; C82.2@15.25,103.5 16,103.5 16.25,103.25 ; J9.10@39.77,57.46 40.23,57 41.875,57 v1(42.375,57.5) ; J9.6@39.77,62.54 41.335,62.54 R118.1@41.5,62.375 ; J9.4@39.77,65.08 41.545,65.08 R115.1@41.625,65
  Bottom Layer w0.35: C143.1@3.375,101.875 3.375,101.475 3.8,101.05 ; U17.3@26.9,102.5 29,102.5 ; R37.1@58.875,63.875 59.375,63.375 v1(60.25,63.375) ; v1(62.5,63.375) 63.375,63.375 R29.1@63.875,63.875 ; R71.1@65.75,69.575 66.2,69.125 70.625,69.125 R97.1@71,69.5
  other v1: 40.375,2.5 86.125,3.25 97.625,3.75 110.125,4.125 31.375,5.625 78.125,5.875 69.375,6 40.125,6.125 85.75,8.25 120.5,8.625 103.125,8.75 111.625,8.875 40,9.875 23.375,11.125 97,11.625 104,13.25 81,14 86,14 60,14.25 42.125,14.375 124.875,14.375 52.125,15.375 48.125,15.75 120.75,18 85.125,18.125 128.125,18.5 157,18.5 50,19.5 109.875,20.25 117.75,20.5 114.375,20.625 38,21.5 10,21.875 130,24 103.5,24.25 99.625,24.5 109.125,24.5 83.25,25 50.125,25.25 42,25.375 126,25.625 77.5,25.75 143.5,26.375 153.875,26.5 106.625,26.75 65.75,27.5 157.25,28.625 130.75,28.875 48.75,30 52.5,30 85,30 72.25,30.25 143.375,30.25 42.625,30.375 65.75,30.875 112.375,30.875 153.875,31.125 137.625,31.375 103.5,31.5 38.5,32.75 51.375,33.25 109.625,33.25 126.5,33.5 80,34.625 92.5,35 109.5,35 122,35.75 69.75,36 42.25,36.375 48.125,36.375 86.375,38 72.5,38.125 79.25,38.25 110.5,38.25 113.125,38.25 157.5,38.25 101.875,38.375 129.875,38.375 47.125,39 126,39 93.5,39.125 69.875,39.75 52.25,40 109,40.75 70,41.5 103.5,42 107.625,42.5 53.25,43 96.625,43.625 70.25,44 93.5,44.125 126,44.125 105.625,44.5 120.75,44.5 150.125,45.375 122.625,45.875 16.625,46 103.5,46.5 70,46.75 156.875,46.875 93.375,47.625 102,48 91,48.125 112.75,48.125 96.25,49 72,49.25 123,49.25 36.5,49.75 39.25,49.75 111,49.875 150.125,50.125 17.25,51 99,51 140.5,51 109,51.875 97.875,52.125 123.25,52.375 131.25,52.375 91.75,53.25 27.5,53.75 88.625,53.875 74.125,54.125 42.375,55 77.125,55.875 79.25,56.375 157.125,56.375 123.25,56.75 125.85,57.1 114.4,57.3 18.5,57.75 127.875,57.875 79.125,58.375 85,58.5 84,59.5 27.375,60 42.375,60 79,60.875 126.75,62.375 141.625,62.375 101.8,62.4 103.6,62.4 105.2,62.4 106.8,62.4 108.8,62.4 110.8,62.4 112.8,62.4 114.4,62.4 122.8,62.4 124.8,62.4 92,62.425 92.875,62.425 93.95,62.425 84.125,62.5 133.25,62.5 146.125,62.625 42.375,62.75 24.75,64.75 84.25,65 42.75,65.5 84.75,66 24.75,67 128,67.375 114.4,67.6 125.75,68.2 123.125,68.375 79,68.5 79.25,70.375 126,71.75 123.125,72 135.375,72.125 96.125,72.625 157.125,72.625 109,73 94.25,73.75 142,74.375 99.75,74.75 111,75 122.875,75.625 101,75.75 102.375,77 113,77.375 103.875,78.25 145,79.625 105.25,79.875 154.5,79.875 5.25,80.125 123.875,80.5 106.625,81.125 108.375,82.875 94.75,83.5 157.125,84.125 109,84.5 125.875,85.125 122.75,86 109,86.25 126,86.5 94.75,87 110.875,87 113,87.125 127.875,88.875 34,89.25 113.25,91.125 157.375,91.25 126,91.625 122.625,91.75 151.5,94.25 122.625,94.5 44.875,95.125 113.25,95.125 143.25,95.25 54.375,96 130.625,96.25 78.75,97 24.75,98 44.25,98.25 123.75,98.375 143.625,99.125 83.375,99.375 134,99.375 157.375,100.25 126.75,100.5 37.25,100.75 78.125,101.25 44.75,102 41.25,102.5 102.125,104.375 113.875,104.5 127.875,104.75 53.125,105.125 49.625,105.875 47.5,107 86.875,107.125 122.75,107.25 77.125,108 127.5,108.75 114.375,109.25 133.5,109.875 55.75,110.25 122.75,110.5 80.875,110.875 157.5,110.875 74,111 110.25,111.375 129,112.375 33.375,112.625 104.5,113 93.25,113.125 98.25,113.5 121.625,113.875 108.625,114.25 101.25,114.5 82.125,114.625 106.375,114.625 85.875,114.75 79,114.875 56.5,116.75 66.625,116.75 89.375,116.875 94.875,117.375 76.125,117.5 123.875,117.5 31.875,118.25 37.75,118.5 76.125,121 89.125,121 149.75,121.25 128.875,121.625 139.375,121.75 119.25,121.875 48.125,122.375 92,123.25 42.375,123.375 117.375,124.125 76.25,124.625 89.25,124.875 94.75,124.875 47.875,126.375 116.25,126.375 98,126.875 110.75,126.875 101.875,127.375 107.125,127.375 60.25,127.75 65,128.125
  other v2: 105,3 115,3 125,3 135,3 145,3 95.875,3.25 38.25,3.5 96.125,5.75 131,5.75 142.75,6.25 95.375,8.375 153,9.375 95.25,10.5 8,12.75 3.5,13.5 78.5,13.75 75.625,14.75 92.375,14.75 101,15.125 79.75,15.875 95.875,16.5 90,16.625 14.75,16.75 25.5,16.75 101.5,18.375 106,18.625 98.75,18.75 71.125,19.25 92.75,19.5 87.5,19.625 86.25,20 89.625,20.25 77.625,20.5 3.25,22 74,22.5 20,22.75 91.625,23.125 67.5,23.5 72.875,25.875 7.375,26.625 95.625,26.75 145.75,26.75 3.25,27.5 61.75,27.875 87.375,28.375 104,28.375 145.75,29.5 77.625,30 80.5,30 97.5,30.125 92.75,30.25 60.375,31.125 6.5,32.375 65.375,34.375 132.25,34.5 57.375,35.25 61.375,35.625 3.25,38 76.5,38.5 83.75,39.5 61.875,39.75 64.875,40 73.75,41.25 57.625,42 79.25,42.5 73.75,42.625 3.75,43 64.875,43 84.75,43.625 73.875,44.75 145,45.625 53.75,45.75 58.375,46.125 74.25,46.625 4,47.5 59.25,48.625 76.875,49 65.125,49.375 51,50.5 85,51.75 55.5,52.625 58.875,52.875 135,53 127.75,53.25 82.25,53.5 77.25,53.625 48.75,55.125 67.125,60.75 48.75,60.875 69.25,60.875 82.375,61.125 61.375,61.375 65.625,63.875 83,64.625 74.5,65.125 57.625,65.5 27.375,66.125 83.25,66.625 48.75,66.875 60.375,67 68.375,67 80.625,67 57.5,68 44.5,68.625 89.5,68.875 82,69 57.375,70 89.625,70.75 65.875,71.625 70.875,71.625 131,71.75 90.5,73.75 98.625,73.75 27.625,74.125 82.25,74.5 58.875,74.875 61.625,75.25 77.25,75.375 87.25,75.375 71,75.5 66.5,75.875 84.625,75.875 57.875,76 44,76.125 96.125,76.875 66.75,77.375 57.375,77.5 49,78 86.5,78.25 66.75,78.625 80.625,79.75 66.75,79.875 84.375,80 86.625,80.375 55.25,82 101.375,82 127,82.5 85,82.875 74,83.875 77.875,83.875 89.75,84 70.375,84.25 56.5,85.875 130.25,85.875 100,86 105.75,87.25 89.5,87.625 56.875,88.625 59.75,88.75 62.875,88.75 66.375,88.75 132,90 91.5,90.875 55.875,91.5 108,91.5 103,91.75 64.75,92.375 71.75,92.375 82.5,92.625 99,93 76.25,93.25 95,93.75 82.25,94.5 107.5,94.5 103,95 86,95.75 70.5,95.875 63.5,97 94,97 58.75,97.5 66.25,97.5 107.25,97.5 56,98 103.75,98 69.75,98.25 87.375,99.5 93.5,99.5 90.25,99.75 110,100 131,100.5 64.125,100.625 11.5,100.875 5.25,101.125 103.75,101.25 81.375,101.375 29.75,102 97,102 22.175,102.5 85,102.5 57,103 29.75,103.25 8,103.5 66.75,103.75 61.5,104.25 94.25,104.75 2.9,105.575 67.5,105.75 130.25,106 18.75,106.25 58.75,106.75 74.25,107.875 24.5,108.5 65.5,108.5 94,108.75 88.25,109.25 91.5,109.25 96.25,110.25 27.125,110.5 86.75,111.5 28.125,112 2.125,113 64,113 77,113 72.75,115.75 23.5,117 9,117.5 26,119.75 4.25,120.75 28.75,121.5 72.75,121.75 31,122 8.25,122.75 16.25,122.75 20.5,123 26.25,123.75 35.75,124 125,127 135,127 145,127 55,128
  other v3: 11.815,25.675 13.185,25.675 10.675,26.815 11.815,26.815 13.185,26.815 14.325,26.815 10.675,28.185 11.815,28.185 13.185,28.185 14.325,28.185 11.815,29.325 13.185,29.325 25,101.4 23.9,102.5 25,102.5 26.1,102.5 25,103.6 98.125,104 69.6,105 70.4,105 96.925,105 98.125,105 99.325,105 98.125,106
  other v4: 10.5,111.7 12,111.7 9.2,113 10.5,113 12,113 13.3,113 9.2,114.5 10.5,114.5 12,114.5 13.3,114.5 10.5,115.8 12,115.8
GND-USB: J18.5 J18.6 J18.7 J18.8 J18.9 L2.1 | length 12.1
  Signal Layer 1 w1: J18.9@8.4,128.75 8.4,127.45 J18.7@10,125.85 J18.6@15,125.85 16.6,127.45 J18.8@16.6,128.75
GPIO_AIB-1: J28.24 U12.6 | length 30.7
  Top Layer w0.2: v1(4.375,36.875) 6.25,38.75 v1(6.25,47.5)
  Bottom Layer w0.2: v1(4.375,36.875) 3.875,36.375 3.875,28.875 5,27.75 U12.6@9.6,27.75 ; v1(6.25,47.5) 7.32,48.57 J28.24@10.73,48.57
GPIO_AIB-2: J28.26 U12.7 | length 26.4
  Top Layer w0.2: v1(5,36.25) 7.5,38.75 v1(7.5,45)
  Bottom Layer w0.2: v1(5,36.25) 4.375,35.625 4.375,29.125 5.25,28.25 U12.7@9.6,28.25 ; v1(7.5,45) 8.53,46.03 J28.26@10.73,46.03
GVDD: J20.1 R31.1 R36.1 R56.2 | length 85.7
  Top Layer w0.5: v1(89.75,52.5) R36.1@89.75,53.55
  Signal Layer 2 w0.5: J20.1@58.73,93.75 58.73,92.52 60,91.25 87.5,91.25 v1(91.875,86.875) ; v1(89.75,52.5) 91,51.25 94.75,51.25 98.5,55 98.5,72 v1(93,77.5)
  Bottom Layer w0.5: R31.1@90.7,78.75 R56.2@93,78.75 ; v1(91.875,86.875) 93.05,85.7 R56.2@93.05,78.8 ; v1(93,77.5) R56.2@93,78.75 ; R56.2@93.125,78.875 R56.2@93.05,78.8 ; R56.2@93,78.75 R56.2@93.05,78.8
GVDD_A: C36.1 R31.2 TP9.1 U8.12 | length 21.3
  Top Layer w0.25: C36.1@74.7,67 TP9.1@75.625,67 75.837,67.212 U8.12@77.25,67.212
  Bottom Layer w0.25: TP9.1@75.625,67 75.625,67.875 77.25,69.5 79.8,69.5 88.8,78.5 R31.2@88.8,78.75
GVDD_B: C44.1 R36.2 TP10.1 U8.30 | length 5.3
  Top Layer w0.25: U8.30@86.75,57.687 88.263,57.687 C44.1@88.5,57.45
  Top Layer w0.5: C44.1@88.5,57.45 89.3,57.45 89.75,57 TP10.1@89.75,56 R36.2@89.75,54.95
I2C-BUF-EN: R112.1 U3.6 | length 52.5
  Top Layer w0.25: v1(25,73.75) 25,72 22.5,69.5 22.5,67.75 23.75,66.5 23.75,65.125 23.125,64.5 23.125,61.375 23.75,60.75 23.75,59 22.875,58.125 22.875,55.875 23.375,55.375 23.375,52.25 23.125,52 23.125,49.875 25,48 v1(26.25,48)
  Bottom Layer w0.25: v1(25,73.75) 22.5,76.25 22.5,82.5 26.647,86.647 28.625,86.647 29.228,87.25 U3.6@29.65,87.25 ; v1(26.25,48) R112.1@29.3,48
I2S-BUF-EN: R11.1 R12.2 R113.1 U28.2 | length 3.9
  Bottom Layer w0.25: U28.2@33.75,49.26 33.75,48.05 R113.1@33.7,48 34.875,48 34.925,47.95 R12.2@34.925,46.625
INA+: C14.1 C15.1 R73.2 R96.2 | length 4.3
  Bottom Layer w0.25: R73.2@69.5,68.05 69.5,66.925 C15.1@69.55,66.875 69.55,65.525 C14.1@69.5,65.475 71.15,65.475 R96.2@71.175,65.5
INA-: C11.1 C12.1 R68.2 R70.2 | length 4.2
  Bottom Layer w0.25: R70.2@65.575,65.5 67.175,65.5 67.2,65.525 C12.1@67.2,66.875 67.25,66.925 R68.2@67.25,68.05
INB+: C8.1 C9.1 R33.2 R35.2 | length 4.3
  Bottom Layer w0.25: R35.2@58.575,59.875 58.6,59.85 C8.1@60.25,59.85 60.2,59.9 C9.1@60.2,61.25 60.25,61.3 R33.2@60.25,62.425
INB-: C5.1 C6.1 R14.2 R15.2 | length 4.3
  Bottom Layer w0.25: R14.2@62.5,62.425 62.5,61.3 C6.1@62.55,61.25 62.55,59.9 C5.1@62.5,59.85 64.15,59.85 R15.2@64.175,59.875
LRCK: R21.2 TP4.1 U8.47 | length 68.8
  Top Layer w0.25: v1(83.75,68) 85,68 85.482,68.482 U8.47@86.75,68.482
  Signal Layer 2 w0.25: TP4.1@48.75,51.25 56.125,58.625 56.125,71.125 61.75,76.75 77.375,76.75 80.625,73.5 80.625,69.5 82.125,68 v1(83.75,68)
  Bottom Layer w0.25: R21.2@45.5,56.25 46.125,56.25 48.75,53.625 TP4.1@48.75,51.25
LRCLK-EXT: J28.15 U13.2 | length 6.5
  Bottom Layer w0.25: J28.15@13.27,58.73 14.5,57.5 15.625,57.5 17.45,55.675 U13.2@18.525,55.675
LRCLK-IBC: J9.11 R117.2 U22.4 U23.2 | length 9.4
  Bottom Layer w0.15: U22.4@33.84,54.85 37.16,54.85 J9.11@37.23,54.92 ; R117.2@41.5,56.25 U23.2@42.66,56.25
  Bottom Layer w0.2: J9.11@37.23,54.92 38.56,56.25 R117.2@41.5,56.25
LRCLK-MUX: J6.1 U13.5 | length 2.5
  Top Layer w0.25: J6.1@24.935,57.025 J6.1@24.96,57
  Bottom Layer w0.25: U13.5@22.475,56.975 24.935,56.975 J6.1@24.96,57
LRCLK-PSIA: J6.2 U22.2 | length 6.7
  Bottom Layer w0.15: J6.2@27.5,57 30,54.5 U22.2@33.16,54.5
LRCLK-SRC: U7.47 U13.1 | length 62
  Top Layer w0.25: v1@17.5,55.125 17.5,58.625 18.75,59.875 18.75,61.75 18,62.5 18,73.625 v1(18.75,74.375)
  Bottom Layer w0.2: v1(18.75,74.375) 20,75.625 20,83 26.5,89.5 26.5,90.625 30.75,94.875 33.5,94.875 35.5,96.875 35.5,101.25 37.5,103.25 U7.47@39.775,103.25
  Bottom Layer w0.25: v1(17.5,55) 17.525,55.025 U13.1@18.525,55.025
LRCLK-USB: R142.1 U7.38 | length 36.8
  Top Layer w0.25: v1(23.125,121.875) 25.625,121.875 28.25,119.25 28.25,113 30,111.25 31.875,111.25 40,103.125 40,100 v1(41.25,98.75)
  Bottom Layer w0.25: R142.1@20.955,121.875 v1(23.125,121.875) ; U7.38@39.775,98.75 v1(41.25,98.75)
MCLK: R17.2 TP2.1 U8.50 | length 56.3
  Top Layer w0.25: v1(84.5,71.5) 85.613,70.387 U8.50@86.75,70.387
  Signal Layer 2 w0.25: TP2.1@48.75,70 50.25,70 51.25,71 51.25,72.5 59.25,80.5 78.75,80.5 84.5,74.75 v1(84.5,71.5)
  Bottom Layer w0.25: R17.2@45.5,64.375 45.5,66.75 TP2.1@48.75,70
MCLK-EXT: J28.11 U9.2 | length 6.9
  Bottom Layer w0.25: J28.11@13.27,63.81 17.135,67.675 U9.2@18.525,67.675
MCLK-IBC: J9.3 R115.2 U18.4 U19.2 | length 9.5
  Bottom Layer w0.15: U18.4@33.84,65.1 37.21,65.1 J9.3@37.23,65.08 ; R115.2@41.5,64 U19.2@42.66,64
  Bottom Layer w0.2: J9.3@37.23,65.08 38.56,63.75 40.75,63.75 41,64 R115.2@41.5,64
MCLK-MUX: J3.1 U9.5 | length 2.5
  Bottom Layer w0.25: U9.5@22.475,68.975 24.935,68.975 J3.1@24.96,69
MCLK-PSIA: J3.2 U18.2 | length 7.4
  Bottom Layer w0.15: J3.2@27.5,69 31.75,64.75 U18.2@33.16,64.75
MCLK-SEL: J1.1 R66.1 U12.24 U31.6 | length 99.2
  Top Layer w0.25: v2(17.125,27.875) 21.25,32 v1(21.25,38.25) ; v1(27.5,38.25) 38.25,38.25 v1(40,40) ; v1(42.5,48.75) 51.5,48.75 52.5,49.75 52.5,72.5 50.625,74.375 48.105,74.375 J1.1@46.23,76.25
  Bottom Layer w0.25: U12.24@15.4,28.25 16.75,28.25 v2(17.125,27.875) R66.1@17.845,27.875 ; v1(21.25,38.25) v1(27.5,38.25) ; v1(40,40) 42.5,42.5 v1(42.5,48.75) ; U31.6@41.15,87.675 42.45,87.675 43.125,87 43.125,79.355 J1.1@46.23,76.25
MCLK-SRC: U9.1 U31.5 | length 39.6
  Bottom Layer w0.25: U9.1@18.525,67.025 19.275,67.025 20,67.75 20,71.5 21,72.5 37.5,72.5 41.25,76.25 41.25,86.925 U31.5@41.15,87.025
MCLK-XTAL: R130.2 R131.2 R132.1 U31.1 | length 6.9
  Bottom Layer w0.2: U31.1@45.1,88.975 47.15,88.975 R130.2@47.175,89 R131.2@47.175,92 47.175,93.725 R132.1@47.25,93.8
MCLKI: R132.2 U7.25 | length 1.8
  Bottom Layer w0.25: U7.25@46.75,96.775 46.75,95.7 R132.2@47.25,95.2
MODE: J14.2 R90.2 U8.14 U12.22 | length 113.9
  Top Layer w0.25: v2(16.875,29.375) 15.5,28 15.5,22 18.75,18.75 30.25,18.75 31.25,17.75 ; 31.25,17.71 J14.2@58,17.71 59.835,17.71 61.25,19.125 v1(61.25,22.5) ; v1(75.5,66) 77.192,66 U8.14@77.25,65.942
  Bottom Layer w0.25: U12.22@15.4,29.25 16.125,29.25 16.25,29.375 v2(16.875,29.375) ; R90.2@58,15.905 J14.2@58,17.71 ; v1(61.25,22.5) 63.375,24.625 63.375,52.75 75.5,64.875 v1(75.5,66)
MUTE-LED: R50.2 U12.21 | length 22.9
  Bottom Layer w0.2: U12.21@15.4,29.75 15.875,29.75 16.125,30 30.75,30 34.75,26 R50.2@36.5,26
MUX-CTRL_MCU: J37.1 R5.1 R111.1 U12.25 | length 23
  Top Layer w0.2: v1(21.25,27.5) R5.1@22.22,27.5 22.22,37.24 J37.1@24.98,40
  Bottom Layer w0.2: U12.25@15.4,27.75 16.125,27.75 16.625,27.25 19.75,27.25 20,27.5 v1(21.25,27.5) ; R111.1@22.75,40 J37.1@24.98,40
MUX_CTRL: R111.2 U9.6 U11.6 U13.6 U14.6 | length 34.4
  Bottom Layer w0.254: 21.175,50.325 U14.6@22.475,50.325 ; R111.2@21.75,40 21,40.75 v1(21,46) 21,51.25 21.25,51.5 21.25,54.5 21,54.75 21,56.25 ; U13.6@22.475,56.325 21.075,56.325 21,56.25 ; U11.6@22.475,62.325 21.075,62.325 21,62.25 ; U9.6@22.475,68.325 21.325,68.325 21,68 21,62.25 ; 21,56.25 21,62.25
NetC1_1: C1.1 J29.1 L3.2 R4.1 U16.6 | length 8.9
  Top Layer w0.25: v2(69,107.25) 69,106.75 R4.1@69.5,106.25
  Bottom Layer w0.25: v2@69,107.275 69.35,106.925 69.75,106.525 U16.6@69.75,105.95
  Bottom Layer w0.75: L3.2@68.55,108.875 68.925,109.25 C1.1@68.925,112.125 68.925,114.655 J29.1@69,114.73
NetC4_2: C4.2 U17.7 | length 1.3
  Bottom Layer w0.25: U17.7@25.5,100.6 25.5,99.7 C4.2@25.75,99.45
NetC6_2: C6.2 C7.2 R29.2 | length 2.8
  Bottom Layer w0.25: C6.2@63.95,61.25 63.95,62.5 R29.2@64,62.55 64.025,62.575 C7.2@65.5,62.575
NetC9_2: C9.2 C10.2 R37.2 | length 2.8
  Bottom Layer w0.25: C10.2@57.25,62.575 57.275,62.55 R37.2@58.75,62.55 58.8,62.5 C9.2@58.8,61.25
NetC12_2: C12.2 C13.2 R71.2 | length 2.8
  Bottom Layer w0.25: C13.2@64.25,68.2 64.275,68.175 R71.2@65.75,68.175 65.8,68.125 C12.2@65.8,66.875
NetC15_2: C15.2 C16.2 R97.2 | length 2.8
  Bottom Layer w0.25: C15.2@70.95,66.875 70.95,68.125 R97.2@71,68.175 72.475,68.175 C16.2@72.5,68.2
NetC20_2: C20.2 J5.3 | length 10.6
  Top Layer w0.25: J5.3@40,116.2 41.8,116.2 43.5,114.5 43.5,110.5 42.75,109.75 C20.2@41.5,109.75 ; J5.3@40,116.25 J5.3@40.025,116.225
NetC22_1: C22.1 U10.9 | length 3.3
  Bottom Layer w0.25: U10.9@98.925,106.9 98.925,110.05 C22.1@99,110.125
NetC26_1: C26.1 U10.2 | length 1.6
  Bottom Layer w0.25: U10.2@98.925,103.1 98.925,101.575 C26.1@99,101.5
NetC34_2: C34.2 R58.1 R84.2 U10.6 | length 5.1
  Bottom Layer w0.25: R58.1@92.5,105.5 92.95,105.95 C34.2@92.95,106.75 R84.2@94,106.75 94.15,106.9 U10.6@96.525,106.9
NetC35_1: C35.1 U10.7 | length 2.2
  Bottom Layer w0.25: C35.1@96.575,108.75 97.325,108 U10.7@97.325,106.9
NetC39_1: C39.1 J27.1 U15.3 | length 16.4
  Bottom Layer w0.75: J27.1@68.77,93.75 72.25,93.75 73.5,95 C39.1@73.5,99 74.75,99 74.7,99.05 U15.3@74.7,104.85
NetC46_2: C46.2 R32.1 | length 1.7
  Bottom Layer w0.25: C46.2@98.85,78.75 R32.1@100.55,78.75
NetC62_1: C62.1 R61.1 R65.2 R95.2 | length 4.1
  Bottom Layer w0.25: R61.1@72.225,73.75 72.225,73.225 72.325,73.125 C62.1@73.375,73.125 74.3,73.125 R95.2@74.425,73.25 R65.2@74.425,74.5
NetC62_2: C62.2 R72.1 R88.2 R98.2 | length 4.1
  Bottom Layer w0.25: R72.1@72.225,71.5 72.225,72.1 72.25,72.125 C62.2@73.375,72.125 74.3,72.125 R98.2@74.425,72 R88.2@74.425,70.75
NetC66_2: C66.2 U8.44 | length 4.9
  Top Layer w0.25: U8.44@86.75,66.577 89.327,66.577 C66.2@91,68.25
NetC68_2: C68.2 U8.43 | length 7.7
  Top Layer w0.25: U8.43@86.75,65.942 89.443,65.942 90.75,67.25 92.75,67.25 93,67.5 C68.2@93,68.3
NetC73_1: C73.1 U8.11 | length 2.8
  Top Layer w0.25: C73.1@74.5,67.875 74.528,67.847 U8.11@77.25,67.847 U8.11@77.278,67.875
NetC75_1: C75.1 U8.6 | length 1.6
  Top Layer w0.25: C75.1@75.75,70.875 75.898,71.022 U8.6@77.25,71.022 U8.6@77.272,71
NetC75_2: C75.2 U8.8 | length 1.6
  Top Layer w0.25: C75.2@75.75,69.875 75.873,69.752 U8.8@77.25,69.752 U8.8@77.252,69.75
